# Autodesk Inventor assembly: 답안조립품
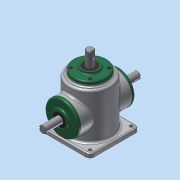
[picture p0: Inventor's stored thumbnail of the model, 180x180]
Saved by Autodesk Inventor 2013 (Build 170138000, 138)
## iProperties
Created: 2015-10
Part Number: 답안조립품
Document SubType Name: Assembly
Designer: Administrator
Author: Administrator
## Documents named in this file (14)
- C:\Users\Administrator\Desktop\451008V1019\답안조립품.iam
- C:\Users\Administrator\Desktop\451008V1019\본체.ipt
- C:\Users\Administrator\Desktop\451008V1019\서브 축.ipt
- 서브 축.ipt
- C:\Users\Administrator\Desktop\451008V1019\베어링 6203.ipt
- C:\Users\Administrator\Desktop\451008V1019\키 4x4.ipt
- C:\Users\Administrator\Desktop\451008V1019\서브 베벨기어.ipt
- C:\Users\Administrator\Desktop\451008V1019\커버.ipt
- C:\Users\Administrator\Desktop\451008V1019\오일실.ipt
- C:\Users\Administrator\Desktop\451008V1019\메인 축.ipt
- 메인 축.ipt
- C:\Users\Administrator\Desktop\451008V1019\키 5x5.ipt
- C:\Users\Administrator\Desktop\451008V1019\메인 베벨기어.ipt
- C:\Users\Administrator\Desktop\451008V1019\M4.ipt
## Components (12 placed, 1 different names)
1. M4:1
2. M4:4
3. M4:5
4. M4:6
5. M4:2
6. M4:7
7. M4:8
8. M4:9
9. M4:3
10. M4:10
11. M4:11
12. M4:12
